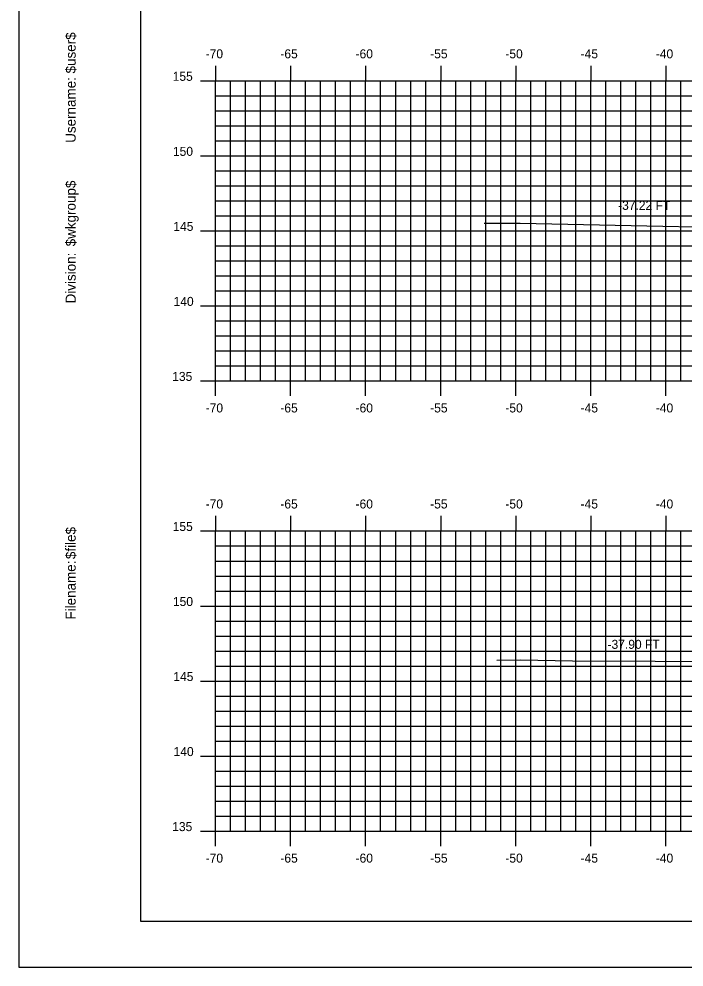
# Model space of a CAD drawing. Extents: x 1144972 to 1145142, y 608981 to 609091.
# Drawn here: x 1144972.3 to 1145016.6, y 608981.3 to 609044.5 of the extents above; entities that cross this region are included whole.
import ezdxf

# ---------------------------------------------------------------- set-up
doc = ezdxf.new("R2010")
doc.units = 0
for name, color, linetype in [('BORDER', 7, 'Continuous'), ('D_Text_Standard', 7, 'Continuous'), ('H_V ANNOTATION', 7, 'Continuous'), ('MAJOR', 7, 'Continuous'), ('MINOR', 7, 'Continuous'), ('PLOT BOUNDARY', 7, 'Continuous'), ('S_Roadway_Centerline', 7, 'Continuous')]:
    doc.layers.add(name, color=color, linetype=linetype)

msp = doc.modelspace()

# ---------------------------------------------------------------- linework, layer by layer
at = {"layer": 'BORDER'}
msp.add_lwpolyline([(1144980.376, 608984.335), (1145140.376, 608984.335), (1145140.376, 609089.335), (1144980.376, 609089.335)], close=True, dxfattribs=at)
at = {"layer": 'MAJOR'}
for p, q in [((1144985.375, 609041.337), (1144985.375, 609040.335)), ((1144990.375, 609041.337), (1144990.375, 609040.335)), ((1144995.375, 609041.337), (1144995.375, 609040.335)), ((1145000.375, 609041.337), (1145000.375, 609040.335)), ((1145005.375, 609041.337), (1145005.375, 609040.335)), ((1145010.375, 609041.337), (1145010.375, 609040.335)), ((1145015.375, 609041.337), (1145015.375, 609040.335)), ((1144984.373, 609040.335), (1144985.375, 609040.335)), ((1144985.375, 609040.335), (1145125.375, 609040.335)), ((1144985.375, 609020.335), (1144985.375, 609040.335)), ((1144985.375, 609020.335), (1144985.375, 609040.335)), ((1144985.375, 609040.335), (1145125.375, 609040.335)), ((1144990.375, 609020.335), (1144990.375, 609040.335)), ((1144995.375, 609020.335), (1144995.375, 609040.335)), ((1145000.375, 609020.335), (1145000.375, 609040.335)), ((1145005.375, 609020.335), (1145005.375, 609040.335)), ((1145010.375, 609020.335), (1145010.375, 609040.335)), ((1145015.375, 609020.335), (1145015.375, 609040.335)), ((1144984.373, 609035.335), (1144985.375, 609035.335)), ((1144985.375, 609035.335), (1145125.375, 609035.335)), ((1144984.373, 609030.335), (1144985.375, 609030.335)), ((1144985.375, 609030.335), (1145125.375, 609030.335)), ((1144984.373, 609025.335), (1144985.375, 609025.335)), ((1144985.375, 609025.335), (1145125.375, 609025.335)), ((1144984.373, 609020.335), (1144985.375, 609020.335)), ((1144985.375, 609020.335), (1145125.375, 609020.335)), ((1144985.375, 609020.335), (1145125.375, 609020.335)), ((1144985.375, 609019.333), (1144985.375, 609020.335)), ((1144990.375, 609019.333), (1144990.375, 609020.335)), ((1144995.375, 609019.333), (1144995.375, 609020.335)), ((1145000.375, 609019.333), (1145000.375, 609020.335)), ((1145005.375, 609019.333), (1145005.375, 609020.335)), ((1145010.375, 609019.333), (1145010.375, 609020.335)), ((1145015.375, 609019.333), (1145015.375, 609020.335)), ((1144985.375, 609011.337), (1144985.375, 609010.335)), ((1144990.375, 609011.337), (1144990.375, 609010.335)), ((1144995.375, 609011.337), (1144995.375, 609010.335)), ((1145000.375, 609011.337), (1145000.375, 609010.335)), ((1145005.375, 609011.337), (1145005.375, 609010.335)), ((1145010.375, 609011.337), (1145010.375, 609010.335)), ((1145015.375, 609011.337), (1145015.375, 609010.335)), ((1144984.373, 609010.335), (1144985.375, 609010.335)), ((1144985.375, 609010.335), (1145125.375, 609010.335)), ((1144985.375, 608990.335), (1144985.375, 609010.335)), ((1144985.375, 608990.335), (1144985.375, 609010.335)), ((1144985.375, 609010.335), (1145125.375, 609010.335)), ((1144990.375, 608990.335), (1144990.375, 609010.335)), ((1144995.375, 608990.335), (1144995.375, 609010.335)), ((1145000.375, 608990.335), (1145000.375, 609010.335)), ((1145005.375, 608990.335), (1145005.375, 609010.335)), ((1145010.375, 608990.335), (1145010.375, 609010.335)), ((1145015.375, 608990.335), (1145015.375, 609010.335)), ((1144984.373, 609005.335), (1144985.375, 609005.335)), ((1144985.375, 609005.335), (1145125.375, 609005.335)), ((1144984.373, 609000.335), (1144985.375, 609000.335)), ((1144985.375, 609000.335), (1145125.375, 609000.335)), ((1144984.373, 608995.335), (1144985.375, 608995.335)), ((1144985.375, 608995.335), (1145125.375, 608995.335)), ((1144984.373, 608990.335), (1144985.375, 608990.335)), ((1144985.375, 608990.335), (1145125.375, 608990.335)), ((1144985.375, 608990.335), (1145125.375, 608990.335)), ((1144985.375, 608989.333), (1144985.375, 608990.335)), ((1144990.375, 608989.333), (1144990.375, 608990.335)), ((1144995.375, 608989.333), (1144995.375, 608990.335)), ((1145000.375, 608989.333), (1145000.375, 608990.335)), ((1145005.375, 608989.333), (1145005.375, 608990.335)), ((1145010.375, 608989.333), (1145010.375, 608990.335)), ((1145015.375, 608989.333), (1145015.375, 608990.335))]:
    msp.add_line(p, q, dxfattribs=at)
at = {"layer": 'MINOR'}
for p, q in [((1144986.375, 609020.335), (1144986.375, 609040.335)), ((1144987.375, 609020.335), (1144987.375, 609040.335)), ((1144988.375, 609020.335), (1144988.375, 609040.335)), ((1144989.375, 609020.335), (1144989.375, 609040.335)), ((1144991.375, 609020.335), (1144991.375, 609040.335)), ((1144992.375, 609020.335), (1144992.375, 609040.335)), ((1144993.375, 609020.335), (1144993.375, 609040.335)), ((1144994.375, 609020.335), (1144994.375, 609040.335)), ((1144996.375, 609020.335), (1144996.375, 609040.335)), ((1144997.375, 609020.335), (1144997.375, 609040.335)), ((1144998.375, 609020.335), (1144998.375, 609040.335)), ((1144999.375, 609020.335), (1144999.375, 609040.335)), ((1145001.375, 609020.335), (1145001.375, 609040.335)), ((1145002.375, 609020.335), (1145002.375, 609040.335)), ((1145003.375, 609020.335), (1145003.375, 609040.335)), ((1145004.375, 609020.335), (1145004.375, 609040.335)), ((1145006.375, 609020.335), (1145006.375, 609040.335)), ((1145007.375, 609020.335), (1145007.375, 609040.335)), ((1145008.375, 609020.335), (1145008.375, 609040.335)), ((1145009.375, 609020.335), (1145009.375, 609040.335)), ((1145011.375, 609020.335), (1145011.375, 609040.335)), ((1145012.375, 609020.335), (1145012.375, 609040.335)), ((1145013.375, 609020.335), (1145013.375, 609040.335)), ((1145014.375, 609020.335), (1145014.375, 609040.335)), ((1145016.375, 609020.335), (1145016.375, 609040.335)), ((1144985.375, 609039.335), (1145125.375, 609039.335)), ((1144985.375, 609039.335), (1144986.377, 609039.335)), ((1144985.375, 609038.335), (1145125.375, 609038.335)), ((1144985.375, 609038.335), (1144986.377, 609038.335)), ((1144985.375, 609037.335), (1145125.375, 609037.335)), ((1144985.375, 609037.335), (1144986.377, 609037.335)), ((1144985.375, 609036.335), (1145125.375, 609036.335)), ((1144985.375, 609036.335), (1144986.377, 609036.335)), ((1144985.375, 609034.335), (1145125.375, 609034.335)), ((1144985.375, 609034.335), (1144986.377, 609034.335)), ((1144985.375, 609033.335), (1145125.375, 609033.335)), ((1144985.375, 609033.335), (1144986.377, 609033.335)), ((1144985.375, 609032.335), (1145125.375, 609032.335)), ((1144985.375, 609032.335), (1144986.377, 609032.335)), ((1144985.375, 609031.335), (1145125.375, 609031.335)), ((1144985.375, 609031.335), (1144986.377, 609031.335)), ((1144985.375, 609029.335), (1145125.375, 609029.335)), ((1144985.375, 609029.335), (1144986.377, 609029.335)), ((1144985.375, 609028.335), (1145125.375, 609028.335)), ((1144985.375, 609028.335), (1144986.377, 609028.335)), ((1144985.375, 609027.335), (1145125.375, 609027.335)), ((1144985.375, 609027.335), (1144986.377, 609027.335)), ((1144985.375, 609026.335), (1145125.375, 609026.335)), ((1144985.375, 609026.335), (1144986.377, 609026.335)), ((1144985.375, 609024.335), (1145125.375, 609024.335)), ((1144985.375, 609024.335), (1144986.377, 609024.335)), ((1144985.375, 609023.335), (1145125.375, 609023.335)), ((1144985.375, 609023.335), (1144986.377, 609023.335)), ((1144985.375, 609022.335), (1145125.375, 609022.335)), ((1144985.375, 609022.335), (1144986.377, 609022.335)), ((1144985.375, 609021.335), (1145125.375, 609021.335)), ((1144985.375, 609021.335), (1144986.377, 609021.335)), ((1144986.375, 608990.335), (1144986.375, 609010.335)), ((1144987.375, 608990.335), (1144987.375, 609010.335)), ((1144988.375, 608990.335), (1144988.375, 609010.335)), ((1144989.375, 608990.335), (1144989.375, 609010.335)), ((1144991.375, 608990.335), (1144991.375, 609010.335)), ((1144992.375, 608990.335), (1144992.375, 609010.335)), ((1144993.375, 608990.335), (1144993.375, 609010.335)), ((1144994.375, 608990.335), (1144994.375, 609010.335)), ((1144996.375, 608990.335), (1144996.375, 609010.335)), ((1144997.375, 608990.335), (1144997.375, 609010.335)), ((1144998.375, 608990.335), (1144998.375, 609010.335)), ((1144999.375, 608990.335), (1144999.375, 609010.335)), ((1145001.375, 608990.335), (1145001.375, 609010.335)), ((1145002.375, 608990.335), (1145002.375, 609010.335)), ((1145003.375, 608990.335), (1145003.375, 609010.335)), ((1145004.375, 608990.335), (1145004.375, 609010.335)), ((1145006.375, 608990.335), (1145006.375, 609010.335)), ((1145007.375, 608990.335), (1145007.375, 609010.335)), ((1145008.375, 608990.335), (1145008.375, 609010.335)), ((1145009.375, 608990.335), (1145009.375, 609010.335)), ((1145011.375, 608990.335), (1145011.375, 609010.335)), ((1145012.375, 608990.335), (1145012.375, 609010.335)), ((1145013.375, 608990.335), (1145013.375, 609010.335)), ((1145014.375, 608990.335), (1145014.375, 609010.335)), ((1145016.375, 608990.335), (1145016.375, 609010.335)), ((1144985.375, 609009.335), (1145125.375, 609009.335)), ((1144985.375, 609009.335), (1144986.377, 609009.335)), ((1144985.375, 609008.335), (1145125.375, 609008.335)), ((1144985.375, 609008.335), (1144986.377, 609008.335)), ((1144985.375, 609007.335), (1145125.375, 609007.335)), ((1144985.375, 609007.335), (1144986.377, 609007.335)), ((1144985.375, 609006.335), (1145125.375, 609006.335)), ((1144985.375, 609006.335), (1144986.377, 609006.335)), ((1144985.375, 609004.335), (1145125.375, 609004.335)), ((1144985.375, 609004.335), (1144986.377, 609004.335)), ((1144985.375, 609003.335), (1145125.375, 609003.335)), ((1144985.375, 609003.335), (1144986.377, 609003.335)), ((1144985.375, 609002.335), (1145125.375, 609002.335)), ((1144985.375, 609002.335), (1144986.377, 609002.335)), ((1144985.375, 609001.335), (1145125.375, 609001.335)), ((1144985.375, 609001.335), (1144986.377, 609001.335)), ((1144985.375, 608999.335), (1145125.375, 608999.335)), ((1144985.375, 608999.335), (1144986.377, 608999.335)), ((1144985.375, 608998.335), (1145125.375, 608998.335)), ((1144985.375, 608998.335), (1144986.377, 608998.335)), ((1144985.375, 608997.335), (1145125.375, 608997.335)), ((1144985.375, 608997.335), (1144986.377, 608997.335)), ((1144985.375, 608996.335), (1145125.375, 608996.335)), ((1144985.375, 608996.335), (1144986.377, 608996.335)), ((1144985.375, 608994.335), (1145125.375, 608994.335)), ((1144985.375, 608994.335), (1144986.377, 608994.335)), ((1144985.375, 608993.335), (1145125.375, 608993.335)), ((1144985.375, 608993.335), (1144986.377, 608993.335)), ((1144985.375, 608992.335), (1145125.375, 608992.335)), ((1144985.375, 608992.335), (1144986.377, 608992.335)), ((1144985.375, 608991.335), (1145125.375, 608991.335)), ((1144985.375, 608991.335), (1144986.377, 608991.335))]:
    msp.add_line(p, q, dxfattribs=at)
at = {"layer": 'PLOT BOUNDARY'}
msp.add_lwpolyline([(1144972.282, 608981.276), (1145142.282, 608981.276), (1145142.282, 609091.276), (1144972.282, 609091.276)], close=True, dxfattribs=at)
at = {"layer": 'S_Roadway_Centerline'}
for points in [[(1145003.273, 609030.859), (1145005.674, 609030.858), (1145026.787, 609030.408), (1145027.556, 609030.232), (1145034.637, 609028.885), (1145034.944, 609028.954), (1145038.524, 609029.722), (1145040.621, 609029.878), (1145040.81, 609029.897), (1145041.855, 609029.932), (1145051.869, 609030.242), (1145062.239, 609030.04), (1145063.168, 609030.012), (1145063.576, 609029.981), (1145067.267, 609029.729), (1145070.324, 609029.106), (1145070.484, 609029.059), (1145070.938, 609029.17), (1145076.33, 609029.906), (1145081.681, 609029.961), (1145099.892, 609030.068)], [(1145004.115, 609001.735), (1145005.693, 609001.744), (1145009.155, 609001.689), (1145025.656, 609001.61), (1145031.824, 609000.263), (1145034.049, 608999.793), (1145036.738, 609000.354), (1145037.982, 609000.651), (1145039.938, 609000.901), (1145040.734, 609000.893), (1145048.301, 609001.069), (1145051.97, 609001.089), (1145053.987, 609000.998), (1145063.171, 609000.834), (1145064.043, 609000.749), (1145067.23, 609000.521), (1145070.819, 609000.016), (1145071.439, 608999.914), (1145077.139, 609000.29), (1145077.857, 609000.331), (1145083.938, 609000.124), (1145100.699, 608999.529)]]:
    msp.add_lwpolyline(points, dxfattribs=at)

# ---------------------------------------------------------------- texts
at = {"layer": 'BORDER'}
for s, p in [('$user$', (1144976.061, 609040.827)), ('Username:', (1144976.061, 609036.203)), ('$wkgroup$', (1144976.061, 609029.305)), ('Division:', (1144976.061, 609025.501)), ('$file$', (1144976.061, 609008.461)), ('Filename:', (1144976.061, 609004.433))]:
    msp.add_text(s, height=0.6696, rotation=90, dxfattribs=at).set_placement(p)
at = {"layer": 'D_Text_Standard'}
for s, p in [('-37.22 FT', (1145012.19, 609031.737)), ('-37.90 FT', (1145011.485, 609002.482))]:
    msp.add_text(s, height=0.6, dxfattribs=at).set_placement(p)
at = {"layer": 'H_V ANNOTATION'}
for s, p in [('-70', (1144984.717, 609041.835)), ('-65', (1144989.693, 609041.835)), ('-60', (1144994.701, 609041.835)), ('-55', (1144999.672, 609041.835)), ('-50', (1145004.68, 609041.835)), ('-45', (1145009.693, 609041.835)), ('-40', (1145014.701, 609041.835)), ('155', (1144982.521, 609040.335)), ('150', (1144982.537, 609035.335)), ('145', (1144982.564, 609030.335)), ('140', (1144982.58, 609025.335)), ('135', (1144982.489, 609020.335)), ('-70', (1144984.717, 609018.235)), ('-65', (1144989.693, 609018.235)), ('-60', (1144994.701, 609018.235)), ('-55', (1144999.672, 609018.235)), ('-50', (1145004.68, 609018.235)), ('-45', (1145009.693, 609018.235)), ('-40', (1145014.701, 609018.235)), ('-70', (1144984.717, 609011.835)), ('-65', (1144989.693, 609011.835)), ('-60', (1144994.701, 609011.835)), ('-55', (1144999.672, 609011.835)), ('-50', (1145004.68, 609011.835)), ('-45', (1145009.693, 609011.835)), ('-40', (1145014.701, 609011.835)), ('155', (1144982.521, 609010.335)), ('150', (1144982.537, 609005.335)), ('145', (1144982.564, 609000.335)), ('140', (1144982.58, 608995.335)), ('135', (1144982.489, 608990.335)), ('-70', (1144984.717, 608988.235)), ('-65', (1144989.693, 608988.235)), ('-60', (1144994.701, 608988.235)), ('-55', (1144999.672, 608988.235)), ('-50', (1145004.68, 608988.235)), ('-45', (1145009.693, 608988.235)), ('-40', (1145014.701, 608988.235))]:
    msp.add_text(s, height=0.6, dxfattribs=at).set_placement(p)
at = {"layer": 'MAJOR'}
for p in [(1144985.371, 609020.335), (1144985.371, 608990.335)]:
    msp.add_text('-', height=0.006, dxfattribs=at).set_placement(p)

doc.saveas('drawing.dxf')
